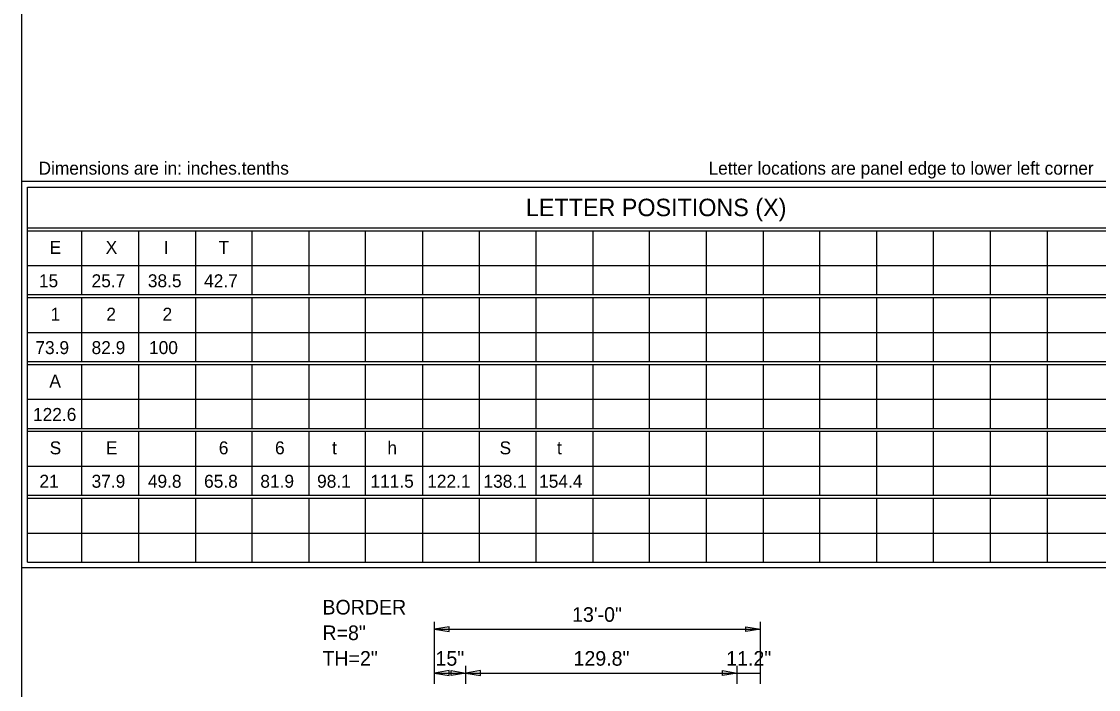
# Model space of a CAD drawing. Extents: x 2149934 to 2150188, y 145114 to 145238.
# Drawn here: x 2150076.32 to 2150119.25, y 145167.44 to 145194.08 of the extents above; entities that cross this region are included whole.
import ezdxf

# ---------------------------------------------------------------- set-up
doc = ezdxf.new("R2010")
doc.units = 0
doc.layers.add('GSDIMS', color=7, linetype='Continuous')
doc.layers.add('Level 1', color=7, linetype='Continuous')

msp = doc.modelspace()

# ---------------------------------------------------------------- linework, layer by layer
at = {"layer": 'GSDIMS'}
for p, q in [((2150092.778, 145169.405), (2150092.778, 145170.134)), ((2150105.779, 145169.405), (2150105.779, 145170.134)), ((2150092.778, 145169.842), (2150105.779, 145169.842)), ((2150092.778, 145167.655), (2150092.778, 145169.405)), ((2150105.779, 145167.655), (2150105.779, 145169.405)), ((2150092.778, 145167.655), (2150092.778, 145168.384)), ((2150094.028, 145167.655), (2150094.028, 145168.384)), ((2150094.028, 145167.655), (2150094.028, 145168.384)), ((2150104.844, 145167.655), (2150104.844, 145168.384)), ((2150104.844, 145167.655), (2150104.844, 145168.384)), ((2150105.779, 145167.655), (2150105.779, 145168.384)), ((2150092.778, 145168.092), (2150094.028, 145168.092)), ((2150094.028, 145168.092), (2150104.844, 145168.092)), ((2150104.844, 145168.092), (2150105.779, 145168.092))]:
    msp.add_line(p, q, dxfattribs=at)
for points in [[(2150092.778, 145169.842), (2150093.362, 145169.745), (2150093.362, 145169.94)], [(2150105.779, 145169.842), (2150105.195, 145169.745), (2150105.195, 145169.94)], [(2150092.778, 145168.092), (2150093.362, 145167.995), (2150093.362, 145168.19)], [(2150094.028, 145168.092), (2150093.445, 145167.995), (2150093.445, 145168.19)], [(2150094.028, 145168.092), (2150094.612, 145167.995), (2150094.612, 145168.19)], [(2150104.844, 145168.092), (2150104.261, 145167.995), (2150104.261, 145168.19)]]:
    msp.add_lwpolyline(points, close=True, dxfattribs=at)
at = {"layer": 'Level 1'}
for p, q in [((2150076.316, 145216.512), (2150076.316, 145117.388)), ((2150076.316, 145187.705), (2150121.342, 145187.705)), ((2150076.548, 145185.849), (2150134.843, 145185.849)), ((2150076.548, 145185.733), (2150134.843, 145185.733)), ((2150078.704, 145185.733), (2150078.704, 145183.183)), ((2150080.977, 145185.733), (2150080.977, 145183.183)), ((2150083.25, 145185.733), (2150083.25, 145183.183)), ((2150085.499, 145185.733), (2150085.499, 145183.183)), ((2150087.772, 145185.733), (2150087.772, 145183.183)), ((2150090.021, 145185.733), (2150090.021, 145183.183)), ((2150092.294, 145185.733), (2150092.294, 145183.183)), ((2150094.566, 145185.733), (2150094.566, 145183.183)), ((2150096.816, 145185.733), (2150096.816, 145183.183)), ((2150099.088, 145185.733), (2150099.088, 145183.183)), ((2150101.337, 145185.733), (2150101.337, 145183.183)), ((2150103.61, 145185.733), (2150103.61, 145183.183)), ((2150105.883, 145185.733), (2150105.883, 145183.183)), ((2150108.132, 145185.733), (2150108.132, 145183.183)), ((2150110.405, 145185.733), (2150110.405, 145183.183)), ((2150112.654, 145185.733), (2150112.654, 145183.183)), ((2150114.927, 145185.733), (2150114.927, 145183.183)), ((2150117.199, 145185.733), (2150117.199, 145183.183)), ((2150076.548, 145184.342), (2150126.185, 145184.342)), ((2150076.548, 145183.183), (2150134.843, 145183.183)), ((2150076.548, 145183.067), (2150134.843, 145183.067)), ((2150078.704, 145183.067), (2150078.704, 145180.516)), ((2150080.977, 145183.067), (2150080.977, 145180.516)), ((2150083.25, 145183.067), (2150083.25, 145180.516)), ((2150085.499, 145183.067), (2150085.499, 145180.516)), ((2150087.772, 145183.067), (2150087.772, 145180.516)), ((2150090.021, 145183.067), (2150090.021, 145180.516)), ((2150092.294, 145183.067), (2150092.294, 145180.516)), ((2150094.566, 145183.067), (2150094.566, 145180.516)), ((2150096.816, 145183.067), (2150096.816, 145180.516)), ((2150099.088, 145183.067), (2150099.088, 145180.516)), ((2150101.337, 145183.067), (2150101.337, 145180.516)), ((2150103.61, 145183.067), (2150103.61, 145180.516)), ((2150105.883, 145183.067), (2150105.883, 145180.516)), ((2150108.132, 145183.067), (2150108.132, 145180.516)), ((2150110.405, 145183.067), (2150110.405, 145180.516)), ((2150112.654, 145183.067), (2150112.654, 145180.516)), ((2150114.927, 145183.067), (2150114.927, 145180.516)), ((2150117.199, 145183.067), (2150117.199, 145180.516)), ((2150076.548, 145181.675), (2150126.185, 145181.675)), ((2150076.548, 145180.516), (2150134.843, 145180.516)), ((2150076.548, 145180.4), (2150134.843, 145180.4)), ((2150078.704, 145180.4), (2150078.704, 145177.849)), ((2150080.977, 145180.4), (2150080.977, 145177.849)), ((2150083.25, 145180.4), (2150083.25, 145177.849)), ((2150085.499, 145180.4), (2150085.499, 145177.849)), ((2150087.772, 145180.4), (2150087.772, 145177.849)), ((2150090.021, 145180.4), (2150090.021, 145177.849)), ((2150092.294, 145180.4), (2150092.294, 145177.849)), ((2150094.566, 145180.4), (2150094.566, 145177.849)), ((2150096.816, 145180.4), (2150096.816, 145177.849)), ((2150099.088, 145180.4), (2150099.088, 145177.849)), ((2150101.337, 145180.4), (2150101.337, 145177.849)), ((2150103.61, 145180.4), (2150103.61, 145177.849)), ((2150105.883, 145180.4), (2150105.883, 145177.849)), ((2150108.132, 145180.4), (2150108.132, 145177.849)), ((2150110.405, 145180.4), (2150110.405, 145177.849)), ((2150112.654, 145180.4), (2150112.654, 145177.849)), ((2150114.927, 145180.4), (2150114.927, 145177.849)), ((2150117.199, 145180.4), (2150117.199, 145177.849)), ((2150076.548, 145179.008), (2150126.185, 145179.008)), ((2150076.548, 145177.849), (2150134.843, 145177.849)), ((2150076.548, 145177.733), (2150134.843, 145177.733)), ((2150078.704, 145177.733), (2150078.704, 145175.182)), ((2150080.977, 145177.733), (2150080.977, 145175.182)), ((2150083.25, 145177.733), (2150083.25, 145175.182)), ((2150085.499, 145177.733), (2150085.499, 145175.182)), ((2150087.772, 145177.733), (2150087.772, 145175.182)), ((2150090.021, 145177.733), (2150090.021, 145175.182)), ((2150092.294, 145177.733), (2150092.294, 145175.182)), ((2150094.566, 145177.733), (2150094.566, 145175.182)), ((2150096.816, 145177.733), (2150096.816, 145175.182)), ((2150099.088, 145177.733), (2150099.088, 145175.182)), ((2150101.337, 145177.733), (2150101.337, 145175.182)), ((2150103.61, 145177.733), (2150103.61, 145175.182)), ((2150105.883, 145177.733), (2150105.883, 145175.182)), ((2150108.132, 145177.733), (2150108.132, 145175.182)), ((2150110.405, 145177.733), (2150110.405, 145175.182)), ((2150112.654, 145177.733), (2150112.654, 145175.182)), ((2150114.927, 145177.733), (2150114.927, 145175.182)), ((2150117.199, 145177.733), (2150117.199, 145175.182)), ((2150076.548, 145176.342), (2150126.185, 145176.342)), ((2150076.548, 145175.182), (2150134.843, 145175.182)), ((2150076.548, 145175.066), (2150134.843, 145175.066)), ((2150078.704, 145175.066), (2150078.704, 145172.515)), ((2150080.977, 145175.066), (2150080.977, 145172.515)), ((2150083.25, 145175.066), (2150083.25, 145172.515)), ((2150085.499, 145175.066), (2150085.499, 145172.515)), ((2150087.772, 145175.066), (2150087.772, 145172.515)), ((2150090.021, 145175.066), (2150090.021, 145172.515)), ((2150092.294, 145175.066), (2150092.294, 145172.515)), ((2150094.566, 145175.066), (2150094.566, 145172.515)), ((2150096.816, 145175.066), (2150096.816, 145172.515)), ((2150099.088, 145175.066), (2150099.088, 145172.515)), ((2150101.337, 145175.066), (2150101.337, 145172.515)), ((2150103.61, 145175.066), (2150103.61, 145172.515)), ((2150105.883, 145175.066), (2150105.883, 145172.515)), ((2150108.132, 145175.066), (2150108.132, 145172.515)), ((2150110.405, 145175.066), (2150110.405, 145172.515)), ((2150112.654, 145175.066), (2150112.654, 145172.515)), ((2150114.927, 145175.066), (2150114.927, 145172.515)), ((2150117.199, 145175.066), (2150117.199, 145172.515)), ((2150076.548, 145173.675), (2150126.185, 145173.675)), ((2150135.447, 145172.284), (2150076.316, 145172.284)), ((2150076.548, 145172.515), (2150134.843, 145172.515))]:
    msp.add_line(p, q, dxfattribs=at)
msp.add_lwpolyline([(2150076.548, 145172.515), (2150076.548, 145187.473), (2150134.843, 145187.473), (2150134.843, 145172.515)], dxfattribs=at)

# ---------------------------------------------------------------- texts
at = {"layer": 'GSDIMS'}
for s, p in [('BORDER', (2150088.312, 145170.426)), ('13\'-0"', (2150098.264, 145170.134)), ('R=8"', (2150088.312, 145169.405)), ('TH=2"', (2150088.312, 145168.384)), ('15"', (2150092.819, 145168.384)), ('129.8"', (2150098.322, 145168.384)), ('11.2"', (2150104.409, 145168.384))]:
    msp.add_text(s, height=0.5833, dxfattribs=at).set_placement(p)
at = {"layer": 'Level 1'}
for s, height, p in [('Dimensions are in: inches.tenths', 0.51652, (2150076.993, 145187.968)), ('Letter locations are panel edge to lower left corner', 0.51652, (2150103.701, 145187.968)), ('LETTER POSITIONS (X)', 0.69555, (2150096.422, 145186.313)), ('E', 0.517, (2150077.437, 145184.81)), ('X', 0.517, (2150079.67, 145184.81)), ('I', 0.517, (2150081.989, 145184.81)), ('T', 0.517, (2150084.167, 145184.81)), ('15', 0.5165, (2150077.008, 145183.478)), ('25.7', 0.5165, (2150079.109, 145183.478)), ('38.5', 0.5165, (2150081.351, 145183.478)), ('42.7', 0.5165, (2150083.593, 145183.478)), ('1', 0.517, (2150077.474, 145182.145)), ('2', 0.517, (2150079.695, 145182.145)), ('2', 0.517, (2150081.937, 145182.145)), ('73.9', 0.5165, (2150076.867, 145180.812)), ('82.9', 0.5165, (2150079.109, 145180.813)), ('100', 0.5165, (2150081.398, 145180.813)), ('A', 0.517, (2150077.425, 145179.479)), ('122.6', 0.5165, (2150076.773, 145178.147)), ('h', 0.517, (2150090.9, 145176.814)), ('S', 0.517, (2150077.437, 145176.814)), ('E', 0.517, (2150079.679, 145176.814)), ('6', 0.517, (2150084.179, 145176.814)), ('6', 0.517, (2150086.421, 145176.814)), ('t', 0.517, (2150088.693, 145176.814)), ('S', 0.517, (2150095.372, 145176.814)), ('t', 0.517, (2150097.661, 145176.814)), ('21', 0.5165, (2150077.029, 145175.482)), ('37.9', 0.5165, (2150079.109, 145175.482)), ('49.8', 0.5165, (2150081.351, 145175.482)), ('65.8', 0.5165, (2150083.593, 145175.482)), ('81.9', 0.5165, (2150085.835, 145175.482)), ('98.1', 0.5165, (2150088.098, 145175.482)), ('111.5', 0.5165, (2150090.225, 145175.482)), ('122.1', 0.5165, (2150092.488, 145175.482)), ('138.1', 0.5165, (2150094.73, 145175.482)), ('154.4', 0.5165, (2150096.948, 145175.482))]:
    msp.add_text(s, height=height, dxfattribs=at).set_placement(p)

doc.saveas('drawing.dxf')
